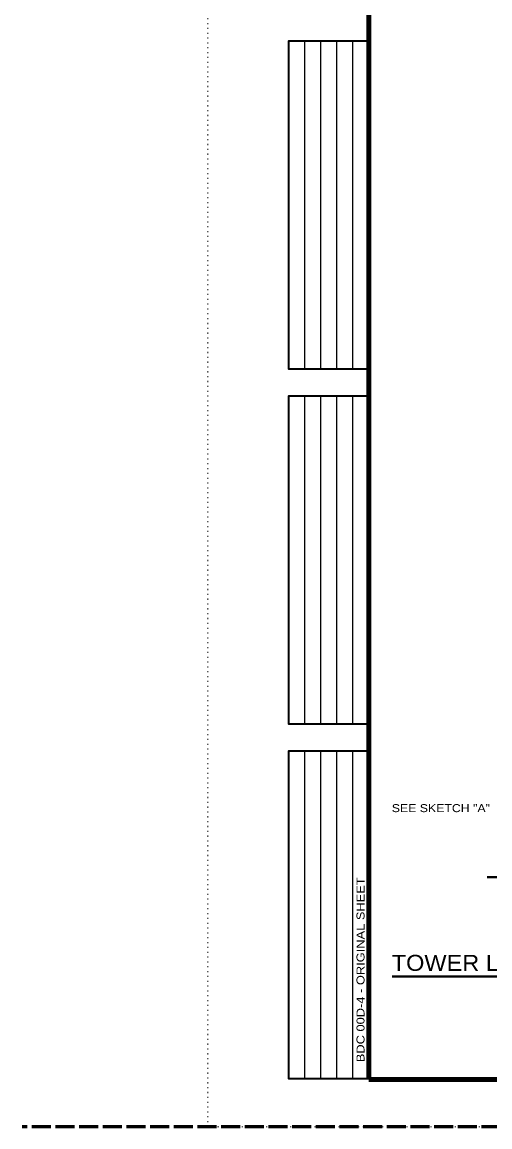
# Model space of a CAD drawing. Extents: x 312583 to 312854, y 144419 to 144597.
# Drawn here: x 312583.5 to 312628, y 144418.6 to 144523.7 of the extents above; entities that cross this region are included whole.
import ezdxf
from ezdxf.enums import TextEntityAlignment as Align

# ---------------------------------------------------------------- set-up
doc = ezdxf.new("R2010")
doc.units = 0
doc.header["$LTSCALE"] = 0.3
doc.linetypes.add('DOTTED', pattern=[1.5, 0.3, -1.2])
doc.linetypes.add('LONG_DASHED', pattern=[7.5, 6, -1.5])
for name, color, linetype, lineweight in [('1', 7, 'Continuous', 13), ('2', 7, 'Continuous', 13), ('61', 7, 'LONG_DASHED', 60), ('63', 7, 'DOTTED', 13)]:
    doc.layers.add(name, color=color, linetype=linetype, lineweight=lineweight)

msp = doc.modelspace()

# ---------------------------------------------------------------- linework, layer by layer
at = {"layer": '1', "lineweight": 25}
for p, q in [((312610.4087, 144490.6573), (312610.4087, 144521.8756)), ((312611.9315, 144490.6573), (312611.9315, 144521.8756)), ((312613.4543, 144490.6573), (312613.4543, 144521.8756)), ((312614.9772, 144490.6573), (312614.9772, 144521.8756)), ((312610.4087, 144456.901), (312610.4087, 144488.1192)), ((312611.9315, 144456.901), (312611.9315, 144488.1192)), ((312613.4543, 144456.901), (312613.4543, 144488.1192)), ((312614.9772, 144456.901), (312614.9772, 144488.1192)), ((312610.4087, 144423.1446), (312610.4087, 144454.3629)), ((312611.9315, 144423.1446), (312611.9315, 144454.3629)), ((312613.4543, 144423.1446), (312613.4543, 144454.3629)), ((312614.9772, 144423.1446), (312614.9772, 144454.3629))]:
    msp.add_line(p, q, dxfattribs=at)
at = {"layer": '1', "lineweight": 40}
msp.add_line((312645.6341, 144442.3419), (312627.7478, 144442.3419), dxfattribs=at)
at = {"layer": '1', "lineweight": 158}
msp.add_line((312616.5, 144423.0846), (312849, 144423.0846), dxfattribs=at)
msp.add_lwpolyline([(312616.5, 144423.1446), (312616.5, 144585.0846), (312849, 144585.0846)], dxfattribs=at)
at = {"layer": '1', "lineweight": 35}
for points in [[(312616.5, 144490.6573), (312608.8858, 144490.6573), (312608.8858, 144521.8756), (312616.5, 144521.8756)], [(312616.5, 144456.901), (312608.8858, 144456.901), (312608.8858, 144488.1192), (312616.5, 144488.1192)], [(312616.5, 144423.1446), (312608.8858, 144423.1446), (312608.8858, 144454.3629), (312616.5, 144454.3629)]]:
    msp.add_lwpolyline(points, dxfattribs=at)
at = {"layer": '2', "lineweight": 40}
msp.add_line((312618.7257, 144432.8992), (312660.3432, 144432.8992), dxfattribs=at)
at = {"layer": '61'}
msp.add_line((312851.75, 144418.5846), (312583.526, 144418.5846), dxfattribs=at)
at = {"layer": '63'}
msp.add_line((312601.2, 144418.5846), (312601.2, 144596.7846), dxfattribs=at)
msp.add_lwpolyline([(312601.2, 144418.5846), (312853.5, 144418.5846), (312853.5, 144596.7846)], dxfattribs=at)

# ---------------------------------------------------------------- texts
at = {"layer": '1', "width": 1.2}
msp.add_text('BDC 00D-4 - ORIGINAL SHEET', height=0.7614, rotation=90, dxfattribs=at).set_placement((312616.0832, 144424.7374))
at = {"layer": '2', "width": 1.15}
msp.add_text('SEE SKETCH "A"', height=0.76, dxfattribs=at).set_placement((312618.6738, 144448.5202))
at = {"layer": '2', "width": 1.1}
msp.add_text('TOWER LIGHT STANDARD ASSEMBLY', height=1.52, dxfattribs=at).set_placement((312639.2306, 144433.4267), align=Align.CENTER)

doc.saveas('drawing.dxf')
